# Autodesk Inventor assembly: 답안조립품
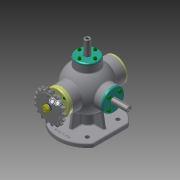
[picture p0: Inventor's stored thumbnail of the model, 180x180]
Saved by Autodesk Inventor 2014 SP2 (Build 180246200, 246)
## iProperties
Created: 2016-03
Part Number: 답안조립품
Document SubType Name: Assembly
Designer: apexhp001
Author: apexhp001
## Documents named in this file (17)
- C:\Users\1sil_ho3333\Desktop\360308V1011\답안조립품.iam
- C:\Users\1sil_ho3333\Desktop\360308V1011\본체.ipt
- C:\Users\1sil_ho3333\Desktop\360308V1011\너트-M8x1.ipt
- C:\Users\1sil_ho3333\Desktop\360308V1011\뒤커버.ipt
- C:\Users\1sil_ho3333\Desktop\360308V1011\베어링- 6202.ipt
- C:\Users\1sil_ho3333\Desktop\360308V1011\본체커버.ipt
- C:\Users\1sil_ho3333\Desktop\360308V1011\볼트 M4x0.7.ipt
- C:\Users\1sil_ho3333\Desktop\360308V1011\스프로킷.ipt
- C:\Users\1sil_ho3333\Desktop\360308V1011\슬라이드 커버.ipt
- C:\Users\1sil_ho3333\Desktop\360308V1011\슬라이드.ipt
- C:\Users\1sil_ho3333\Desktop\360308V1011\앞커버.ipt
- C:\Users\1sil_ho3333\Desktop\360308V1011\오일실.ipt
- C:\Users\1sil_ho3333\Desktop\360308V1011\와셔 8x17.ipt
- C:\Users\1sil_ho3333\Desktop\360308V1011\축.ipt
- C:\Users\1sil_ho3333\Desktop\360308V1011\키 3 x 3 x 12.ipt
- C:\Users\1sil_ho3333\Desktop\360308V1011\스프링1.ipt
- C:\Users\1sil_ho3333\Desktop\360308V1011\스프링2.ipt
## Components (17 placed, 1 different names)
1. M4x0.7x12:5 — 각도:1
2. M4x0.7x12:1 — 각도:2
3. M4x0.7x12:6
4. M4x0.7x12:7
5. M4x0.7x12:8
6. M4x0.7x12:4 — 각도:3
7. M4x0.7x12:9
8. M4x0.7x12:10
9. M4x0.7x12:11
10. M4x0.7x12:3 — 각도:4
11. M4x0.7x12:12
12. M4x0.7x12:13
13. M4x0.7x12:14
14. M4x0.7x12:2 — 각도:5
15. M4x0.7x12:15
16. M4x0.7x12:16
17. M4x0.7x12:17
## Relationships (5: Angle 5)
- 각도:1 [Angle]: M4x0.7x12:5
- 각도:2 [Angle]: M4x0.7x12:1
- 각도:3 [Angle]: M4x0.7x12:4
- 각도:4 [Angle]: M4x0.7x12:3
- 각도:5 [Angle]: M4x0.7x12:2
